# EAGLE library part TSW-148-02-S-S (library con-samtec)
THROUGH-HOLE .025" SQ POST HEADER Source: Samtec TSW.pdf
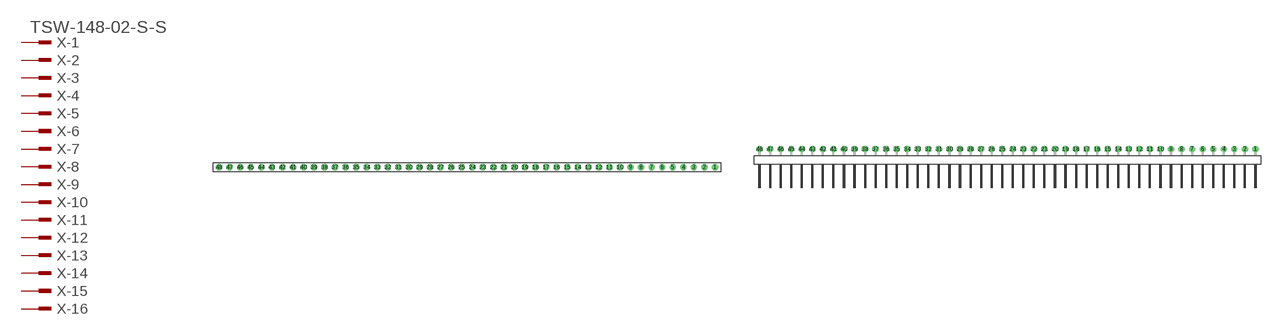
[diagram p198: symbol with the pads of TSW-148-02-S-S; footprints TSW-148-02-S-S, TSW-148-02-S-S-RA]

Designator prefix X; gates -1=MPINV -2=MPIN -3=MPIN -4=MPIN -5=MPIN -6=MPIN -7=MPIN -8=MPIN -9=MPIN -10=MPIN -11=MPIN -12=MPIN -13=MPIN -14=MPIN -15=MPIN -16=MPIN -17=MPIN -18=MPIN -19=MPIN -20=MPIN -21=MPIN -22=MPIN -23=MPIN -24=MPIN -25=MPIN -26=MPIN -27=MPIN -28=MPIN -29=MPIN -30=MPIN -31=MPIN -32=MPIN -33=MPIN -34=MPIN -35=MPIN -36=MPIN -37=MPIN -38=MPIN -39=MPIN -40=MPIN -41=MPIN -42=MPIN -43=MPIN -44=MPIN -45=MPIN -46=MPIN -47=MPIN -48=MPIN

## TSW-148-02-S-S (OC_FARNELL: unknown; OC_NEWARK: unknown)  [TSW-148-02-S-S]
1  -1:1  pas
2  -2:1  pas
3  -3:1  pas
4  -4:1  pas
5  -5:1  pas
6  -6:1  pas
7  -7:1  pas
8  -8:1  pas
9  -9:1  pas
10  -10:1  pas
11  -11:1  pas
12  -12:1  pas
13  -13:1  pas
14  -14:1  pas
15  -15:1  pas
16  -16:1  pas
17  -17:1  pas
18  -18:1  pas
19  -19:1  pas
20  -20:1  pas
21  -21:1  pas
22  -22:1  pas
23  -23:1  pas
24  -24:1  pas
25  -25:1  pas
26  -26:1  pas
27  -27:1  pas
28  -28:1  pas
29  -29:1  pas
30  -30:1  pas
31  -31:1  pas
32  -32:1  pas
33  -33:1  pas
34  -34:1  pas
35  -35:1  pas
36  -36:1  pas
37  -37:1  pas
38  -38:1  pas
39  -39:1  pas
40  -40:1  pas
41  -41:1  pas
42  -42:1  pas
43  -43:1  pas
44  -44:1  pas
45  -45:1  pas
46  -46:1  pas
47  -47:1  pas
48  -48:1  pas

## TSW-148-02-S-S-RA (OC_FARNELL: unknown; OC_NEWARK: unknown)  [TSW-148-02-S-S-RA]
Pads as for TSW-148-02-S-S

## Footprint TSW-148-02-S-S (pad centres in mm)
THROUGH-HOLE .025" SQ POST HEADER Source: Samtec TSW.pdf
drill 1 pad 1.5 octagon: 1 59.69,0; 2 57.15,0; 3 54.61,0; 4 52.07,0; 5 49.53,0; 6 46.99,0; 7 44.45,0; 8 41.91,0; 9 39.37,0; 10 36.83,0; 11 34.29,0; 12 31.75,0; 13 29.21,0; 14 26.67,0; 15 24.13,0; 16 21.59,0; 17 19.05,0; 18 16.51,0; 19 13.97,0; 20 11.43,0; 21 8.89,0; 22 6.35,0; 23 3.81,0; 24 1.27,0; 25 -1.27,0; 26 -3.81,0; 27 -6.35,0; 28 -8.89,0; 29 -11.43,0; 30 -13.97,0; 31 -16.51,0; 32 -19.05,0; 33 -21.59,0; 34 -24.13,0; 35 -26.67,0; 36 -29.21,0; 37 -31.75,0; 38 -34.29,0; 39 -36.83,0; 40 -39.37,0; 41 -41.91,0; 42 -44.45,0; 43 -46.99,0; 44 -49.53,0; 45 -52.07,0; 46 -54.61,0; 47 -57.15,0; 48 -59.69,0

## Footprint TSW-148-02-S-S-RA (pad centres in mm)
THROUGH-HOLE .025" SQ POST HEADER Source: Samtec TSW.pdf
drill 1 pad 1.5 octagon: 1 59.69,1.524; 2 57.15,1.524; 3 54.61,1.524; 4 52.07,1.524; 5 49.53,1.524; 6 46.99,1.524; 7 44.45,1.524; 8 41.91,1.524; 9 39.37,1.524; 10 36.83,1.524; 11 34.29,1.524; 12 31.75,1.524; 13 29.21,1.524; 14 26.67,1.524; 15 24.13,1.524; 16 21.59,1.524; 17 19.05,1.524; 18 16.51,1.524; 19 13.97,1.524; 20 11.43,1.524; 21 8.89,1.524; 22 6.35,1.524; 23 3.81,1.524; 24 1.27,1.524; 25 -1.27,1.524; 26 -3.81,1.524; 27 -6.35,1.524; 28 -8.89,1.524; 29 -11.43,1.524; 30 -13.97,1.524; 31 -16.51,1.524; 32 -19.05,1.524; 33 -21.59,1.524; 34 -24.13,1.524; 35 -26.67,1.524; 36 -29.21,1.524; 37 -31.75,1.524; 38 -34.29,1.524; 39 -36.83,1.524; 40 -39.37,1.524; 41 -41.91,1.524; 42 -44.45,1.524; 43 -46.99,1.524; 44 -49.53,1.524; 45 -52.07,1.524; 46 -54.61,1.524; 47 -57.15,1.524; 48 -59.69,1.524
